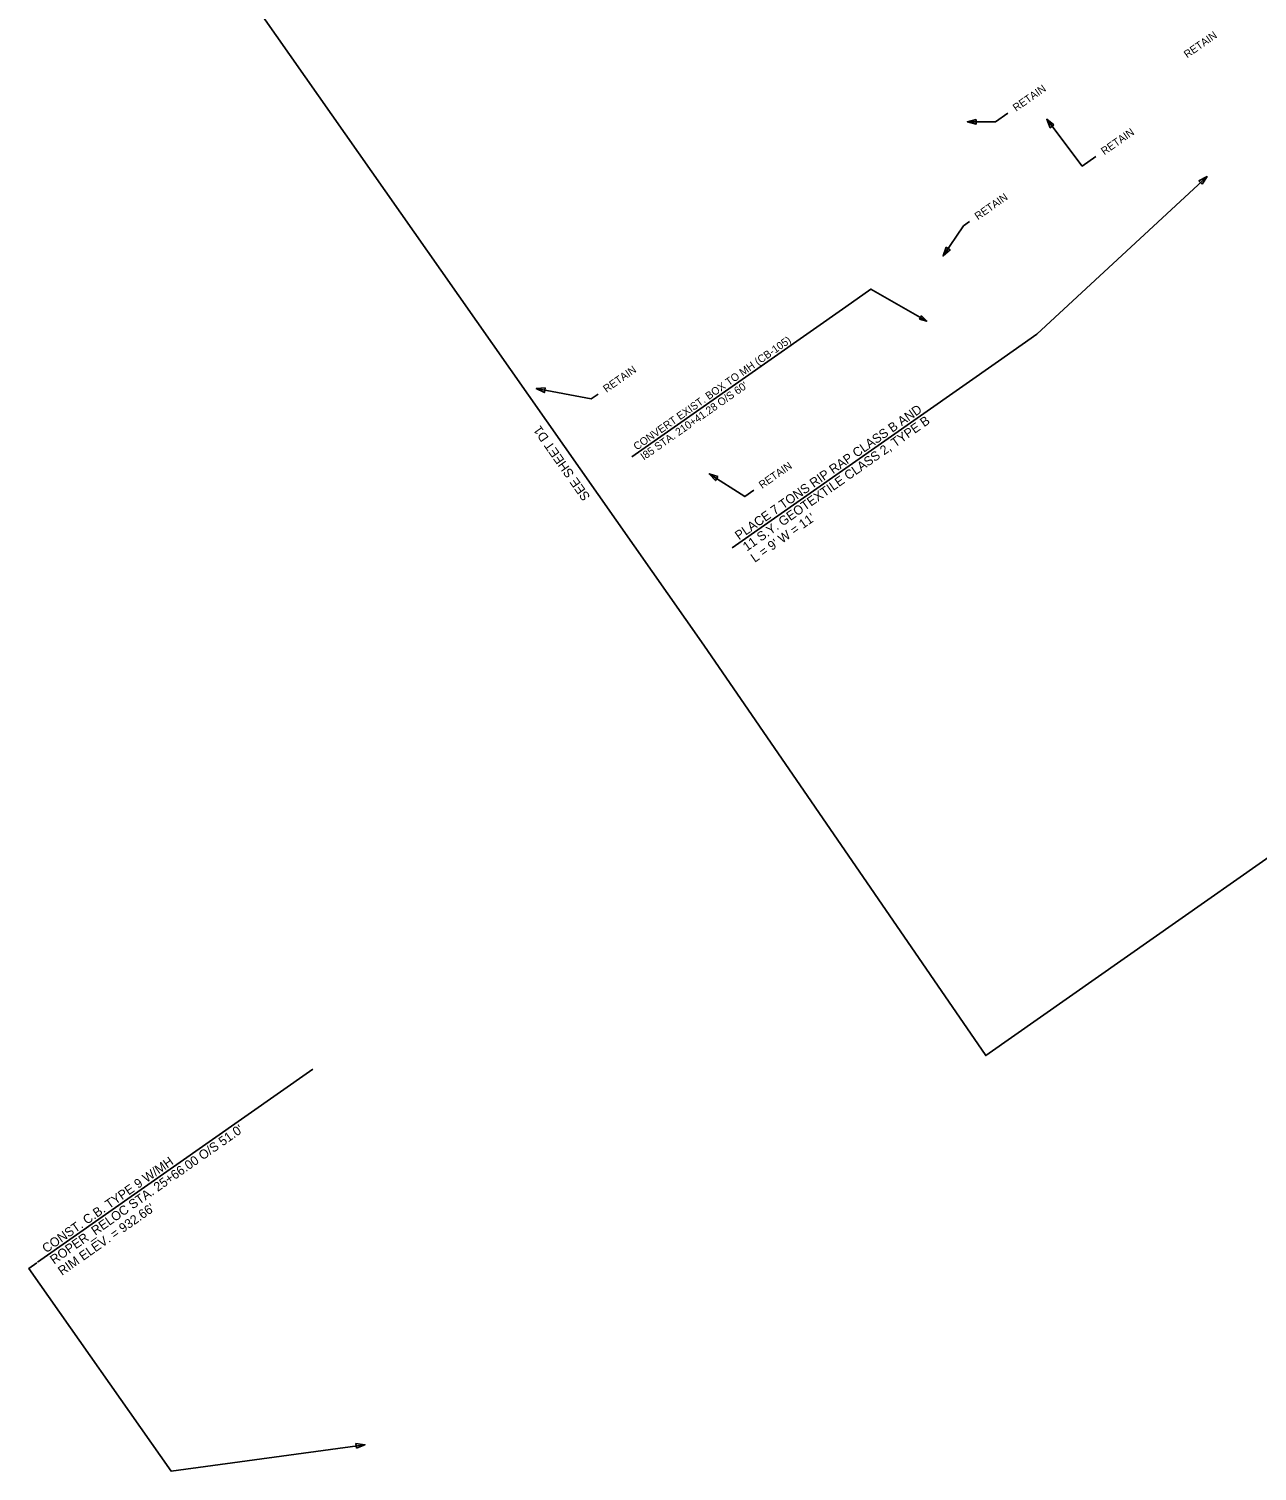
# Model space of a CAD drawing. Extents: x 1603736 to 1605697, y 1088463 to 1090389.
# Drawn here: x 1603736 to 1604540, y 1088463 to 1089408 of the extents above; entities that cross this region are included whole.
import ezdxf

# ---------------------------------------------------------------- set-up
doc = ezdxf.new("R2010")
doc.units = 0
for name, color, linetype in [('Plan_Clip', 7, 'Continuous'), ('RD_SHT_MatchLine', 7, 'Continuous'), ('RD_TX_Drainage', 7, 'Continuous')]:
    doc.layers.add(name, color=color, linetype=linetype)

msp = doc.modelspace()

# ---------------------------------------------------------------- linework, layer by layer
at = {"layer": 'Plan_Clip'}
msp.add_lwpolyline([(1605233.56, 1090111.04), (1605405.83, 1089865.44), (1605593.12, 1089598.42), (1604362.43, 1088735.18), (1604177.81, 1089004.07), (1604005.53, 1089249.68), (1603817.48, 1089517.78), (1604919.05, 1090290.45), (1604939.78, 1090260.89), (1605067.39, 1090350.4)], close=True, dxfattribs=at)
msp.add_lwpolyline([(1605233.56, 1090111.04), (1605405.83, 1089865.44), (1605593.12, 1089598.42), (1604362.43, 1088735.18), (1604177.81, 1089004.07), (1604005.53, 1089249.68), (1603817.48, 1089517.78), (1604919.05, 1090290.45), (1604939.78, 1090260.89), (1605067.39, 1090350.4)], close=True, dxfattribs=at)
msp.add_lwpolyline([(1605233.56, 1090111.04), (1605405.83, 1089865.44), (1605593.12, 1089598.42), (1604362.43, 1088735.18), (1604177.81, 1089004.07), (1604005.53, 1089249.68), (1603817.48, 1089517.78), (1604919.05, 1090290.45), (1604939.78, 1090260.89), (1605067.39, 1090350.4)], close=True, dxfattribs=at)
msp.add_lwpolyline([(1605233.56, 1090111.04), (1605405.83, 1089865.44), (1605593.12, 1089598.42), (1604362.43, 1088735.18), (1604177.81, 1089004.07), (1604005.53, 1089249.68), (1603817.48, 1089517.78), (1604919.05, 1090290.45), (1604939.78, 1090260.89), (1605067.39, 1090350.4)], close=True, dxfattribs=at)
msp.add_lwpolyline([(1605233.56, 1090111.04), (1605405.83, 1089865.44), (1605593.12, 1089598.42), (1604362.43, 1088735.18), (1604177.81, 1089004.07), (1604005.53, 1089249.68), (1603817.48, 1089517.78), (1604919.05, 1090290.45), (1604939.78, 1090260.89), (1605067.39, 1090350.4)], close=True, dxfattribs=at)
msp.add_lwpolyline([(1605233.56, 1090111.04), (1605405.83, 1089865.44), (1605593.12, 1089598.42), (1604362.43, 1088735.18), (1604177.81, 1089004.07), (1604005.53, 1089249.68), (1603817.48, 1089517.78), (1604919.05, 1090290.45), (1604939.78, 1090260.89), (1605067.39, 1090350.4)], close=True, dxfattribs=at)
msp.add_lwpolyline([(1605233.56, 1090111.04), (1605405.83, 1089865.44), (1605593.12, 1089598.42), (1604362.43, 1088735.18), (1604177.81, 1089004.07), (1604005.53, 1089249.68), (1603817.48, 1089517.78), (1604919.05, 1090290.45), (1604939.78, 1090260.89), (1605067.39, 1090350.4)], close=True, dxfattribs=at)
msp.add_lwpolyline([(1605233.56, 1090111.04), (1605405.83, 1089865.44), (1605593.12, 1089598.42), (1604362.43, 1088735.18), (1604177.81, 1089004.07), (1604005.53, 1089249.68), (1603817.48, 1089517.78), (1604919.05, 1090290.45), (1604939.78, 1090260.89), (1605067.39, 1090350.4)], close=True, dxfattribs=at)
at = {"layer": 'RD_TX_Drainage'}
for p, q in [((1604270.76, 1089225.64), (1604130.59, 1089127.32)), ((1604370.8, 1089190.08), (1604196.32, 1089067.69)), ((1603921.67, 1088726.28), (1603741.25, 1088599.73))]:
    msp.add_line(p, q, dxfattribs=at)
for points in [[(1604376.77, 1089352.55), (1604368.69, 1089346.89), (1604350.41, 1089346.81)], [(1604434.55, 1089324.03), (1604425.6, 1089317.76), (1604402.35, 1089348.53)], [(1604370.8, 1089190.08), (1604395.88, 1089207.67), (1604507.34, 1089310.94)], [(1604351.74, 1089281.46), (1604347.83, 1089278.72), (1604334.46, 1089258.93)], [(1604270.76, 1089225.64), (1604287.22, 1089237.19), (1604323.75, 1089216.18)], [(1604108.41, 1089168.41), (1604103.96, 1089165.28), (1604067.91, 1089172.03)], [(1604210.39, 1089105.46), (1604204.47, 1089101.32), (1604181.27, 1089116.25)], [(1603740.7, 1088599.35), (1603735.57, 1088595.74), (1603828.73, 1088462.92), (1603955.75, 1088480.27)]]:
    msp.add_lwpolyline(points, dxfattribs=at)
for points in [[(1604356.2, 1089348.39), (1604350.41, 1089346.81), (1604356.21, 1089345.28)], [(1604407.08, 1089344.85), (1604402.35, 1089348.53), (1604404.6, 1089342.97)], [(1604504.14, 1089305.87), (1604507.34, 1089310.94), (1604502.03, 1089308.14)], [(1604336.41, 1089264.6), (1604334.46, 1089258.93), (1604338.99, 1089262.86)], [(1604318.92, 1089217.47), (1604323.75, 1089216.18), (1604320.21, 1089219.71)], [(1604073.89, 1089172.49), (1604067.91, 1089172.03), (1604073.32, 1089169.43)], [(1604186.98, 1089114.42), (1604181.27, 1089116.25), (1604185.3, 1089111.81)], [(1603950.22, 1088477.95), (1603955.75, 1088480.27), (1603949.8, 1088481.03)]]:
    msp.add_lwpolyline(points, close=True, dxfattribs=at)

# ---------------------------------------------------------------- texts
at = {"layer": 'RD_SHT_MatchLine'}
msp.add_text('SEE SHEET D1', height=6, rotation=125.0981, dxfattribs=at).set_placement((1604103.57, 1089101.24))
at = {"layer": 'RD_TX_Drainage'}
for s, height, p in [('RETAIN', 5, (1604494.34, 1089388.3)), ('RETAIN', 5, (1604382.3, 1089353.38)), ('RETAIN', 5, (1604440.08, 1089324.86)), ('RETAIN', 5, (1604357.27, 1089282.28)), ('CONVERT EXIST. BOX TO MH (CB-105)', 5, (1604133.82, 1089131.42)), ('RETAIN', 5, (1604113.94, 1089169.23)), ("I85 STA. 210+41.28 O/S 60'", 5, (1604138.41, 1089124.87)), ('PLACE 7 TONS RIP RAP CLASS B AND', 6, (1604200.74, 1089072.62)), ('11 S.Y. GEOTEXTILE CLASS 2, TYPE B', 6, (1604205.91, 1089065.25)), ('RETAIN', 5, (1604215.92, 1089106.29)), ("L = 9' W = 11'", 6, (1604211.08, 1089057.89)), ("ROPER_RELOC STA. 25+66.00 O/S 51.0'", 6, (1603752.1, 1088598.18)), ('CONST. C.B. TYPE 9 W/MH', 6, (1603746.94, 1088605.55)), ("RIM ELEV. = 932.66'", 6, (1603757.27, 1088590.82))]:
    msp.add_text(s, height=height, rotation=35.04683, dxfattribs=at).set_placement(p)

doc.saveas('drawing.dxf')
